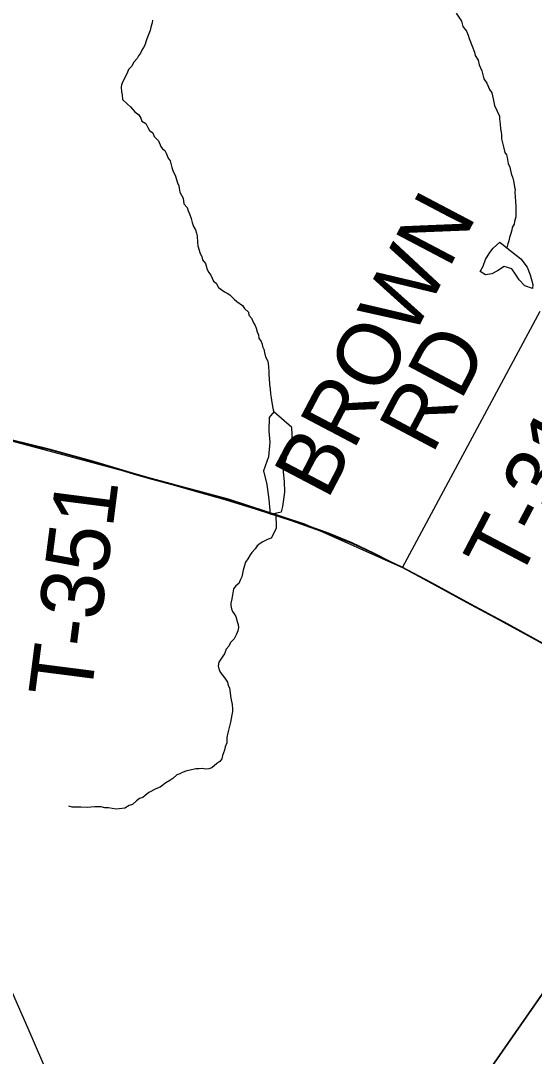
# Model space of a CAD drawing. Extents: x 0 to 39.3, y -3.9 to 22.
# Drawn here: x 5.634 to 6.099, y 17.092 to 18.028 of the extents above; entities that cross this region are included whole.
import ezdxf

# ---------------------------------------------------------------- set-up
doc = ezdxf.new("R2010")
doc.units = 0
for name, color, linetype in [('GM_X_Corporation', 7, 'Continuous'), ('GM_X_Minor_Lake', 7, 'Continuous'), ('GM_X_Minor_River', 7, 'Continuous'), ('GM_X_Rail_Line', 7, 'Continuous'), ('GM_X_State_Route', 7, 'Continuous'), ('GM_X_Township_Road', 7, 'Continuous'), ('GM_X_Township_Road_Text', 7, 'Continuous')]:
    doc.layers.add(name, color=color, linetype=linetype)

msp = doc.modelspace()

# ---------------------------------------------------------------- linework, layer by layer
at = {"layer": 'GM_X_Corporation'}
for points in [[(5.62682, 17.64888), (5.65992, 17.64097), (5.70047, 17.62985), (5.73677, 17.61886), (5.75272, 17.61425), (5.77069, 17.60952), (5.79398, 17.60266), (5.81869, 17.59592), (5.84718, 17.58706), (5.87898, 17.57701), (5.91362, 17.56448), (5.93442, 17.5562), (5.95452, 17.54662), (5.96882, 17.5393), (5.97961, 17.53428), (6.00594, 17.52027), (6.03786, 17.50277), (6.05808, 17.49189), (6.07557, 17.48267), (6.10986, 17.46352)], [(6.10986, 17.46352), (6.07557, 17.48267), (6.05808, 17.49189), (6.03786, 17.50277), (6.00594, 17.52027), (5.97961, 17.53428), (5.96882, 17.5393), (5.95452, 17.54662), (5.93442, 17.5562), (5.91362, 17.56448), (5.87898, 17.57701), (5.84718, 17.58706), (5.81869, 17.59592), (5.79398, 17.60266), (5.77069, 17.60952), (5.75272, 17.61425), (5.73677, 17.61886), (5.70047, 17.62985), (5.65992, 17.64097), (5.62682, 17.64888)], [(6.26673, 17.37817), (6.02556, 17.03189), (5.83978, 16.76515), (5.74399, 16.62887), (5.74241, 16.62664), (5.20279, 15.83764), (5.0728, 15.65196), (4.23761, 14.43621), (4.23345, 14.43016), (3.95356, 14.02275), (3.94742, 14.0138), (3.86924, 13.9), (7.89397, 13.9)], [(6.02556, 17.03189), (6.26673, 17.37817)]]:
    msp.add_lwpolyline(points, dxfattribs=at)
at = {"layer": 'GM_X_Minor_Lake'}
for points in [[(6.05503, 17.79846), (6.05014, 17.80158), (6.05288, 17.80648), (6.05489, 17.81253), (6.0588, 17.81892), (6.06191, 17.82267), (6.06499, 17.82528), (6.06808, 17.82826), (6.07433, 17.82295)], [(6.07433, 17.82295), (6.08683, 17.81311), (6.09279, 17.80541), (6.09533, 17.79852), (6.09784, 17.78973), (6.0974, 17.78632), (6.0906, 17.78872), (6.08537, 17.79413), (6.08203, 17.79913), (6.0787, 17.80413), (6.07189, 17.80615), (6.06573, 17.80208), (6.06075, 17.7995), (6.05503, 17.79846)], [(5.8633, 17.67476), (5.8593, 17.66957), (5.85871, 17.65703), (5.85968, 17.64713), (5.85869, 17.63384), (5.85391, 17.62138), (5.85712, 17.60878), (5.8588, 17.59544), (5.86009, 17.58212), (5.87039, 17.58422)], [(5.87039, 17.58422), (5.87162, 17.58914), (5.87336, 17.60203), (5.87314, 17.61154), (5.87182, 17.62335), (5.87544, 17.63507), (5.88022, 17.64791), (5.87968, 17.66047), (5.8633, 17.67476)]]:
    msp.add_lwpolyline(points, dxfattribs=at)
at = {"layer": 'GM_X_Minor_River'}
for points in [[(6.02849, 18.03525), (6.03331, 18.02794), (6.03437, 18.02335), (6.03772, 18.01911), (6.03918, 18.01528), (6.04027, 18.01222), (6.04281, 18.00533), (6.045, 17.99996), (6.04571, 17.99691), (6.0483, 17.99268), (6.04937, 17.98847), (6.05156, 17.98311), (6.05334, 17.97585), (6.05632, 17.97199), (6.0585, 17.96625), (6.06073, 17.96317), (6.06178, 17.95782), (6.0632, 17.95171), (6.0654, 17.94673), (6.0676, 17.94213), (6.06756, 17.93984), (6.06824, 17.93489), (6.06855, 17.9307), (6.06925, 17.92764), (6.0696, 17.92535), (6.06953, 17.92155), (6.07167, 17.91315), (6.07237, 17.90933), (6.07385, 17.90702), (6.07457, 17.90472), (6.07562, 17.89938), (6.07708, 17.89593), (6.07813, 17.89021), (6.07958, 17.886), (6.0803, 17.8837), (6.081, 17.88027), (6.08134, 17.87798), (6.08169, 17.87569), (6.08165, 17.87341), (6.08226, 17.86503), (6.08257, 17.86046), (6.08241, 17.85095), (6.0812, 17.84679), (6.08078, 17.84452), (6.07921, 17.8415), (6.07878, 17.83884), (6.07758, 17.83506), (6.07677, 17.83241), (6.07596, 17.82938), (6.07516, 17.82674), (6.07433, 17.82295)], [(5.75352, 18.02905), (5.7531, 18.0264), (5.75189, 18.02261), (5.75146, 18.01958), (5.74949, 18.01505), (5.7483, 18.01203), (5.74668, 18.00635), (5.7455, 18.00409), (5.74394, 18.00183), (5.74276, 17.99919), (5.74081, 17.99656), (5.73963, 17.9943), (5.73653, 17.99093), (5.73457, 17.98716), (5.73186, 17.98417), (5.73067, 17.98115), (5.72674, 17.97361), (5.72555, 17.97059), (5.72513, 17.96831), (5.72544, 17.96412), (5.72615, 17.96145), (5.72646, 17.95725), (5.73095, 17.95299), (5.73358, 17.95066), (5.73768, 17.94603), (5.74105, 17.9433), (5.7429, 17.94023), (5.744, 17.93755), (5.74739, 17.93559), (5.74922, 17.93175), (5.7507, 17.92906), (5.75371, 17.92711), (5.75517, 17.92366), (5.75891, 17.91979), (5.7611, 17.9148), (5.76258, 17.9125), (5.76484, 17.91093), (5.76594, 17.90863), (5.76776, 17.90404), (5.76963, 17.90172), (5.77104, 17.89561), (5.77213, 17.89217), (5.77397, 17.88871), (5.77613, 17.88183), (5.77723, 17.87915), (5.77757, 17.87686), (5.77827, 17.87342), (5.78123, 17.86804), (5.7819, 17.86271), (5.78488, 17.85961), (5.78597, 17.85655), (5.78707, 17.85387), (5.78852, 17.84966), (5.78959, 17.84583), (5.79068, 17.84239), (5.79252, 17.83932), (5.79323, 17.83626), (5.79396, 17.83397), (5.79423, 17.82787), (5.79456, 17.82483), (5.79673, 17.81794), (5.7982, 17.81525), (5.79891, 17.81219), (5.80151, 17.80873), (5.80295, 17.80338), (5.80442, 17.80069), (5.80628, 17.79837), (5.80885, 17.793), (5.8111, 17.79106), (5.81332, 17.78722), (5.81857, 17.78332), (5.82122, 17.78213), (5.82347, 17.78057), (5.82759, 17.7767), (5.82983, 17.77437), (5.83509, 17.77086)], [(5.83509, 17.77086), (5.83695, 17.76816), (5.84031, 17.76468), (5.84065, 17.76201), (5.84326, 17.7593), (5.84509, 17.75509), (5.84657, 17.75278), (5.8473, 17.75048), (5.84838, 17.74704), (5.84947, 17.74436), (5.8498, 17.74131), (5.85203, 17.73823), (5.85275, 17.73593), (5.85309, 17.73364), (5.8542, 17.73134), (5.85491, 17.72829), (5.85598, 17.72446), (5.85782, 17.72063), (5.85815, 17.71796), (5.85849, 17.71567), (5.85879, 17.71072), (5.85874, 17.70768), (5.85908, 17.70501), (5.85936, 17.6993), (5.86005, 17.69548), (5.86036, 17.69091), (5.86106, 17.68747), (5.8614, 17.68519), (5.86207, 17.67947), (5.86277, 17.67641), (5.8633, 17.67476)], [(5.86504, 17.58313), (5.86554, 17.56947), (5.86396, 17.56608), (5.86082, 17.56043), (5.85814, 17.55933), (5.85354, 17.55713), (5.85086, 17.55566), (5.84816, 17.55342), (5.84659, 17.55079), (5.84349, 17.54742), (5.84194, 17.54516), (5.83998, 17.54178), (5.83765, 17.53877), (5.83683, 17.53574), (5.83562, 17.53158), (5.83438, 17.52552), (5.83281, 17.5225), (5.83162, 17.51948), (5.82892, 17.51724), (5.82698, 17.51462), (5.8253, 17.50552), (5.82448, 17.50173), (5.82444, 17.49944), (5.82515, 17.49639), (5.82587, 17.49409), (5.82735, 17.49179), (5.82883, 17.48948), (5.83028, 17.48489), (5.83099, 17.48221), (5.83133, 17.47954), (5.8309, 17.47651), (5.8297, 17.47348), (5.82735, 17.46934), (5.82426, 17.46597), (5.82268, 17.46258), (5.82035, 17.45996), (5.81876, 17.4558), (5.8172, 17.45354), (5.81369, 17.44828), (5.81287, 17.44487), (5.81359, 17.44219), (5.81468, 17.43913), (5.81915, 17.43373), (5.82137, 17.43027), (5.82208, 17.42721), (5.82318, 17.42491), (5.82455, 17.41576), (5.82559, 17.41003), (5.8259, 17.40584), (5.82587, 17.40356), (5.82543, 17.40052), (5.82418, 17.39408)], [(5.82418, 17.39408), (5.82256, 17.38802), (5.82174, 17.38423), (5.82091, 17.38006), (5.82082, 17.37512), (5.81925, 17.37172), (5.81881, 17.36869), (5.81683, 17.36378), (5.8164, 17.36074), (5.81446, 17.35849), (5.81177, 17.35664), (5.80714, 17.35253), (5.80446, 17.35182), (5.80142, 17.3515), (5.79838, 17.35193), (5.79572, 17.3516), (5.79268, 17.35165), (5.78772, 17.35059), (5.78466, 17.34989), (5.78046, 17.34844), (5.77816, 17.34734), (5.77548, 17.34625), (5.772, 17.34288), (5.76931, 17.34103), (5.76547, 17.33919), (5.76046, 17.3351), (5.75664, 17.33364), (5.75012, 17.33033), (5.74703, 17.32772), (5.74472, 17.32586), (5.74166, 17.32478), (5.73897, 17.32292), (5.73549, 17.31956), (5.73243, 17.31847), (5.72859, 17.31626), (5.72326, 17.31559), (5.72097, 17.31525), (5.71718, 17.3157), (5.71377, 17.31652), (5.71035, 17.31658), (5.70694, 17.3174), (5.70124, 17.3175), (5.69781, 17.31718), (5.69515, 17.31685), (5.68869, 17.31696), (5.68526, 17.31702), (5.68071, 17.3171), (5.67768, 17.31791)]]:
    msp.add_lwpolyline(points, dxfattribs=at)
at = {"layer": 'GM_X_Rail_Line'}
for points in [[(4.18622, 18.62831), (4.16229, 18.58605), (4.13124, 18.5367), (4.12369, 18.48529), (4.12892, 18.43918), (4.15569, 18.40598), (4.19759, 18.37648), (4.47535, 18.17304), (4.96919, 17.80149), (5.02614, 17.76837), (5.21709, 17.68386), (5.32106, 17.63105), (5.39089, 17.58757), (5.43744, 17.54098), (5.46537, 17.50526), (5.48399, 17.47265), (5.64071, 17.11701), (5.6795, 17.02694), (5.72761, 16.96171), (5.77261, 16.91201), (5.96967, 16.67439), (6.19906, 16.40813)], [(4.18622, 18.62831), (4.5461, 18.29048), (5.02431, 17.8281), (5.05481, 17.80455), (5.09109, 17.79139), (5.82191, 17.59599), (5.89111, 17.57346), (5.98316, 17.53226), (6.18094, 17.42458)]]:
    msp.add_lwpolyline(points, dxfattribs=at)
at = {"layer": 'GM_X_State_Route'}
for points in [[(5.5572, 17.66641), (5.57835, 17.66101), (5.62705, 17.64836), (5.66015, 17.64044), (5.7007, 17.62933), (5.737, 17.61834), (5.75295, 17.61373)], [(5.75295, 17.61373), (5.77092, 17.609), (5.79421, 17.60214), (5.81892, 17.5954), (5.84741, 17.58653), (5.87921, 17.57649), (5.91385, 17.56395), (5.93466, 17.55568), (5.95475, 17.5461), (5.96905, 17.53878), (5.97984, 17.53376)], [(5.97984, 17.53376), (6.00618, 17.51974), (6.0381, 17.50225), (6.05831, 17.49137), (6.07581, 17.48215), (6.11009, 17.463), (6.15773, 17.43746), (6.19781, 17.41583), (6.23457, 17.3962), (6.26696, 17.37764)]]:
    msp.add_lwpolyline(points, dxfattribs=at)
at = {"layer": 'GM_X_Township_Road'}
msp.add_line((5.97984, 17.53376), (6.1044, 17.76572), dxfattribs=at)

# ---------------------------------------------------------------- texts
at = {"layer": 'GM_X_Township_Road_Text'}
for s, rotation, p in [('BROWN', 62.27625, (5.91178, 17.594)), ('RD', 62.10262, (6.00674, 17.63522)), ('T-315', 62.30639, (6.08372, 17.51889)), ('T-351', 82.66533, (5.69754, 17.4138))]:
    msp.add_text(s, height=0.056818, rotation=rotation, dxfattribs=at).set_placement(p)

doc.saveas('drawing.dxf')
